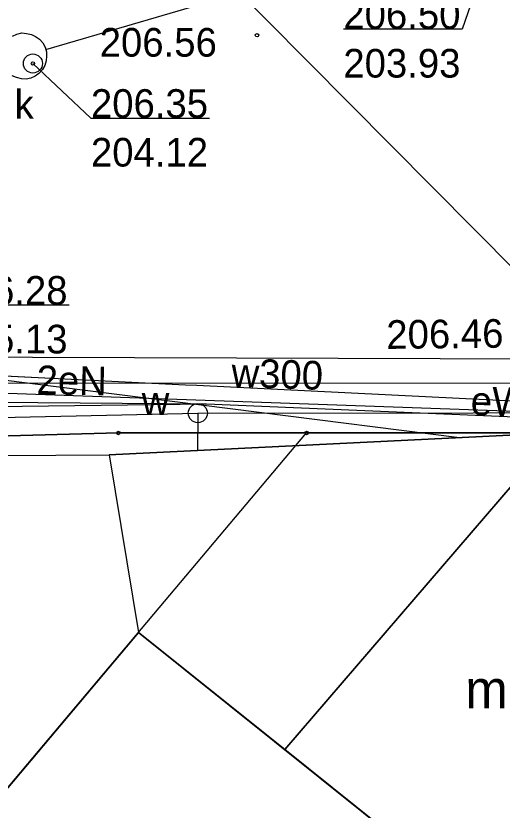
# Model space of a CAD drawing. Extents: x 6512400 to 6513200, y 6022500 to 6022750.
# Drawn here: x 6512782.87 to 6512795.61, y 6022664.87 to 6022685.66 of the extents above; entities that cross this region are included whole.
import ezdxf

# ---------------------------------------------------------------- set-up
doc = ezdxf.new("R2010")
doc.units = 0
for name, color, linetype in [('203-punkt graniczny', 7, 'Continuous'), ('216-obręb ewidencyjny', 7, 'Continuous'), ('217-kontur klasyfikacyjny', 7, 'Continuous'), ('218-kontur użytku gruntowego', 7, 'Continuous'), ('219-działka ewidencyjna', 7, 'Continuous'), ('312-budynek ewidencyjny', 7, 'Continuous'), ('312-oznaczenie budynku ewidencyjnego-Atr117', 7, 'Continuous'), ('320-blok - kondygnacja nadziemna', 7, 'Continuous'), ('chodnik (powierzchnia)', 7, 'Continuous'), ('inna obudowa przewodu - sieć telekomunikacyjna (linia)', 7, 'Continuous'), ('inna obudowa przewodu - sieć wodociągowa (linia)', 7, 'Continuous'), ('komora podziemna - przewód kanalizacyjny (powierzchnia)', 7, 'Continuous'), ('krawężnik (linia)', 7, 'Continuous'), ('przewód elektroenergetyczny (linia)', 7, 'Continuous'), ('przewód elektroenergetyczny (linia)-Atr1', 7, 'Continuous'), ('przewód kanalizacyjny (linia)', 7, 'Continuous'), ('przewód telekomunikacyjny (linia)', 7, 'Continuous'), ('przewód wodociągowy (linia)', 7, 'Continuous'), ('przewód wodociągowy (linia)-Atr1', 7, 'Continuous'), ('punkt o określonej wysokości (sieć kanalizacyjna)', 7, 'Continuous'), ('punkt o określonej wysokości (sieć kanalizacyjna)-Atr2', 7, 'Continuous'), ('punkt o określonej wysokości (sieć kanalizacyjna)-Atr3', 7, 'Continuous'), ('punkt wysokościowy sztuczny', 7, 'Continuous'), ('punkt wysokościowy sztuczny-Atr2', 7, 'Continuous'), ('właz okrągły - siec kanalizacyjna (punkt)', 7, 'Continuous'), ('właz okrągły - siec kanalizacyjna (punkt)-Atr17', 7, 'Continuous'), ('właz okrągły - siec wodociągowa (punkt)', 7, 'Continuous'), ('właz okrągły - siec wodociągowa (punkt)-Atr17', 7, 'Continuous')]:
    doc.layers.add(name, color=color, linetype=linetype)

# ---------------------------------------------------------------- blocks, each defined once
blk = doc.blocks.new('203')
blk.add_circle((0, 0), 0.045)
blk = doc.blocks.new('PW01')
blk.add_circle((0, 0), 0.045)
blk = doc.blocks.new('US22')
blk.add_circle((0, 0), 0.25)
blk = doc.blocks.new('PW02')
blk.add_circle((0, 0), 0.045)

msp = doc.modelspace()

# ---------------------------------------------------------------- linework, layer by layer
at = {"layer": '216-obręb ewidencyjny'}
for points in [[(6512688.62, 6022674.91), (6512702.58, 6022674.18), (6512725.78, 6022672.95), (6512730.35, 6022672.71), (6512735.76, 6022672.94), (6512745.51, 6022673.33), (6512754.87, 6022673.72), (6512768.24, 6022674.27), (6512785.56, 6022674.74), (6512790.49, 6022674.74), (6512796.96, 6022674.74), (6512801.96, 6022670.34), (6512828.67, 6022670.98), (6512833.61, 6022675.02), (6512836.69, 6022675.17), (6512851.94, 6022675.93)], [(6512780.7, 6022581.02), (6512806.2, 6022572.11), (6512806.62, 6022563.51), (6512811.41, 6022558.95), (6512818.47, 6022559.72), (6512828.23, 6022562.62), (6512858.85, 6022571.74), (6512855.78, 6022583.95), (6512853.17, 6022604.51), (6512852.25, 6022608.25), (6512838.47, 6022634.29), (6512825.37, 6022649.66), (6512810.18, 6022663.28), (6512801.96, 6022670.34), (6512796.96, 6022674.74), (6512790.49, 6022674.74), (6512785.56, 6022674.74), (6512768.24, 6022674.27)]]:
    msp.add_lwpolyline(points, dxfattribs=at)
at = {"layer": '217-kontur klasyfikacyjny'}
for points in [[(6512786.09, 6022669.52), (6512777.42, 6022659.24)], [(6512795.54, 6022661.95), (6512786.09, 6022669.52)]]:
    msp.add_lwpolyline(points, dxfattribs=at)
at = {"layer": '218-kontur użytku gruntowego'}
for points in [[(6512785.56, 6022674.74), (6512768.24, 6022674.27)], [(6512768.24, 6022674.27), (6512785.56, 6022674.74)], [(6512796.96, 6022674.74), (6512785.56, 6022674.74)], [(6512785.56, 6022674.74), (6512796.96, 6022674.74)], [(6512786.09, 6022669.52), (6512777.42, 6022659.24)], [(6512777.42, 6022659.24), (6512786.09, 6022669.52)], [(6512795.54, 6022661.95), (6512786.09, 6022669.52)], [(6512786.09, 6022669.52), (6512795.54, 6022661.95)]]:
    msp.add_lwpolyline(points, dxfattribs=at)
at = {"layer": '219-działka ewidencyjna'}
for points in [[(6512785.56, 6022674.74), (6512768.24, 6022674.27)], [(6512777.42, 6022659.24), (6512790.49, 6022674.74)], [(6512785.56, 6022674.74), (6512790.49, 6022674.74)], [(6512796.96, 6022674.74), (6512790.49, 6022674.74)]]:
    msp.add_lwpolyline(points, dxfattribs=at)
at = {"layer": '312-budynek ewidencyjny'}
for points in [[(6512785.32, 6022674.17), (6512797.05, 6022674.74)], [(6512789.92, 6022666.46), (6512797.05, 6022674.74)], [(6512797.05, 6022674.74), (6512789.92, 6022666.46)], [(6512768.55, 6022674.06), (6512785.32, 6022674.17)], [(6512779.23, 6022661.39), (6512786.09, 6022669.52)], [(6512786.09, 6022669.52), (6512779.23, 6022661.39)], [(6512786.09, 6022669.52), (6512789.92, 6022666.46)], [(6512789.92, 6022666.46), (6512786.09, 6022669.52)], [(6512795.54, 6022661.95), (6512789.92, 6022666.46)], [(6512789.92, 6022666.46), (6512795.54, 6022661.95)]]:
    msp.add_lwpolyline(points, dxfattribs=at)
at = {"layer": '320-blok - kondygnacja nadziemna'}
msp.add_lwpolyline([(6512789.92, 6022666.46), (6512797.05, 6022674.74), (6512785.32, 6022674.17), (6512786.09, 6022669.52)], close=True, dxfattribs=at)
at = {"layer": 'chodnik (powierzchnia)'}
msp.add_lwpolyline([(6512768.21, 6022674.06), (6512768.55, 6022674.06), (6512785.32, 6022674.17), (6512797.05, 6022674.74)], dxfattribs=at)
at = {"layer": 'inna obudowa przewodu - sieć telekomunikacyjna (linia)'}
msp.add_lwpolyline([(6512802.54, 6022672.36), (6512802.51, 6022672.39), (6512787.26, 6022687.76), (6512787.22, 6022687.8)], dxfattribs=at)
at = {"layer": 'inna obudowa przewodu - sieć wodociągowa (linia)'}
for points in [[(6512778.01, 6022676.46), (6512787.32, 6022676)], [(6512787.61, 6022675.99), (6512796.6, 6022675.55)]]:
    msp.add_lwpolyline(points, dxfattribs=at)
at = {"layer": 'komora podziemna - przewód kanalizacyjny (powierzchnia)'}
msp.add_lwpolyline([(6512782.79, 6022685.13), (6512782.9, 6022685.18), (6512783.03, 6022685.21), (6512783.15, 6022685.2), (6512783.28, 6022685.17), (6512783.39, 6022685.12), (6512783.49, 6022685.05), (6512783.58, 6022684.95), (6512783.64, 6022684.84), (6512783.68, 6022684.72), (6512783.68, 6022684.6), (6512783.67, 6022684.48), (6512783.63, 6022684.36), (6512783.57, 6022684.25), (6512783.48, 6022684.15), (6512783.38, 6022684.08), (6512783.27, 6022684.03), (6512783.14, 6022684), (6512783.02, 6022684.01), (6512782.89, 6022684.04), (6512782.78, 6022684.09)], dxfattribs=at)
at = {"layer": 'krawężnik (linia)'}
msp.add_lwpolyline([(6512769.23, 6022676.77), (6512772.62, 6022676.76), (6512796.66, 6022676.68), (6512798.51, 6022676.57), (6512799.61, 6022676.46)], dxfattribs=at)
at = {"layer": 'przewód elektroenergetyczny (linia)'}
for points in [[(6512731.37, 6022676.71), (6512731.37, 6022675.58), (6512748.46, 6022675.47), (6512780.13, 6022675.56), (6512787.87, 6022675.5)], [(6512763.38, 6022676.06), (6512798.79, 6022676.04), (6512803.06, 6022673.02), (6512807.84, 6022668.96), (6512815.24, 6022662.53), (6512819.98, 6022657.77), (6512831.6, 6022645.79), (6512834.59, 6022642.25), (6512837.06, 6022638.75), (6512840.02, 6022634.13), (6512842.26, 6022630.04), (6512846.03, 6022621.35), (6512846.58, 6022618.9), (6512847.6, 6022616.23), (6512852.12, 6022605.09), (6512853.39, 6022601.13), (6512855.57, 6022592.48), (6512858.1, 6022582.86), (6512868.09, 6022584.49), (6512870.03, 6022584.23), (6512871.36, 6022584.34), (6512875.65, 6022585.56), (6512879.74, 6022586.61), (6512881.754, 6022587.357)], [(6512776, 6022676.02), (6512799.41, 6022675.19), (6512801.88, 6022673.76), (6512804.18, 6022672.41), (6512807.52, 6022669.86), (6512808.59, 6022669.6), (6512810.5, 6022669.85), (6512831.73, 6022668.71)], [(6512702.603, 6022675.567), (6512731.84, 6022674.22), (6512765.79, 6022675.22), (6512787.87, 6022675.5)], [(6512787.87, 6022675.5), (6512797.4, 6022675.1), (6512801.43, 6022674.21), (6512802.27, 6022673.66)]]:
    msp.add_lwpolyline(points, dxfattribs=at)
at = {"layer": 'przewód kanalizacyjny (linia)'}
for points in [[(6512783.66, 6022684.78), (6512794.77, 6022688.03)], [(6512794.49, 6022674.61), (6512778.74, 6022676.6), (6512778.69, 6022676.95)]]:
    msp.add_lwpolyline(points, dxfattribs=at)
at = {"layer": 'przewód telekomunikacyjny (linia)'}
msp.add_lwpolyline([(6512803.2, 6022671.69), (6512802.51, 6022672.39), (6512787.26, 6022687.76), (6512786.53, 6022688.5)], dxfattribs=at)
at = {"layer": 'przewód wodociągowy (linia)'}
for points in [[(6512776.98, 6022676.45), (6512777.41, 6022676.47), (6512777.83, 6022676.47), (6512787.32, 6022676), (6512787.61, 6022675.99), (6512796.6, 6022675.55), (6512799.85, 6022675.39), (6512814.29, 6022667.35), (6512815.22, 6022667.12), (6512815.2, 6022666.73), (6512814.74, 6022665.5)], [(6512702.579, 6022674.359), (6512731.63, 6022673.98), (6512765.81, 6022675.09), (6512780.05, 6022675.09), (6512787.64, 6022675.26)], [(6512787.64, 6022675.26), (6512787.63, 6022674.27)], [(6512787.64, 6022675.26), (6512802.06, 6022675.28)]]:
    msp.add_lwpolyline(points, dxfattribs=at)
at = {"layer": 'punkt o określonej wysokości (sieć kanalizacyjna)-Atr2'}
for points in [[(6512795.52, 6022688.08), (6512794.56, 6022685.31), (6512791.451, 6022685.31)], [(6512783.32, 6022684.41), (6512784.84, 6022682.98), (6512787.949, 6022682.98)], [(6512778.69, 6022676.95), (6512781.16, 6022678.09), (6512784.269, 6022678.09)]]:
    msp.add_lwpolyline(points, dxfattribs=at)

# ---------------------------------------------------------------- block references
at = {"layer": '203-punkt graniczny'}
for p in [(6512785.56, 6022674.74), (6512790.49, 6022674.74)]:
    msp.add_blockref('203', p, dxfattribs=at)
at = {"layer": 'punkt o określonej wysokości (sieć kanalizacyjna)'}
msp.add_blockref('PW01', (6512783.32, 6022684.41), dxfattribs=at)
at = {"layer": 'punkt wysokościowy sztuczny'}
msp.add_blockref('PW02', (6512789.19, 6022685.15), dxfattribs=at)
at = {"layer": 'właz okrągły - siec kanalizacyjna (punkt)'}
msp.add_blockref('US22', (6512783.32, 6022684.41), dxfattribs=at)
at = {"layer": 'właz okrągły - siec wodociągowa (punkt)'}
msp.add_blockref('US22', (6512787.64, 6022675.26), dxfattribs=at)

# ---------------------------------------------------------------- texts
at = {"layer": '312-oznaczenie budynku ewidencyjnego-Atr117'}
msp.add_text('m2', height=1, dxfattribs=at).set_placement((6512794.645, 6022667.53))
at = {"layer": 'przewód elektroenergetyczny (linia)-Atr1'}
for s, rotation, p in [('2eN', 358.752, (6512783.41, 6022675.76)), ('eWA', 358.456, (6512794.78, 6022675.21))]:
    msp.add_text(s, height=0.75, rotation=rotation, dxfattribs=at).set_placement(p)
at = {"layer": 'przewód wodociągowy (linia)-Atr1'}
msp.add_text('w300', height=0.75, rotation=358.025, dxfattribs=at).set_placement((6512788.51, 6022675.95))
at = {"layer": 'punkt o określonej wysokości (sieć kanalizacyjna)-Atr2'}
for s, p in [('206.50', (6512791.451, 6022685.317)), ('206.35', (6512784.84, 6022682.988)), ('206.28', (6512781.16, 6022678.098))]:
    msp.add_text(s, height=0.75, dxfattribs=at).set_placement(p)
at = {"layer": 'punkt o określonej wysokości (sieć kanalizacyjna)-Atr3'}
for s, p in [('203.93', (6512791.451, 6022684.042)), ('204.12', (6512784.84, 6022681.713)), ('205.13', (6512781.16, 6022676.822))]:
    msp.add_text(s, height=0.75, dxfattribs=at).set_placement(p)
at = {"layer": 'punkt wysokościowy sztuczny-Atr2'}
msp.add_text('206.56', height=0.75, dxfattribs=at).set_placement((6512785.07, 6022684.59))
msp.add_text('206.46', height=0.75, rotation=0.62, dxfattribs=at).set_placement((6512792.58, 6022676.94))
at = {"layer": 'właz okrągły - siec kanalizacyjna (punkt)-Atr17'}
msp.add_text('k', height=0.75, dxfattribs=at).set_placement((6512782.84, 6022682.97))
at = {"layer": 'właz okrągły - siec wodociągowa (punkt)-Atr17'}
msp.add_text('w', height=0.75, dxfattribs=at).set_placement((6512786.17, 6022675.21))

doc.saveas('drawing.dxf')
